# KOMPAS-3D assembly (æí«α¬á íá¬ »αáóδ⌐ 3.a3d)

Referenced files in D:\АСКОН работа\Конкурс HOME\06_Сюваев_Сборная модель танка Т90\ДЕТАЛИ\КОРПУС\МЕТАЛЛ\КОРПУС ШТАМПОВКА\БАКИ\: бак правый 3.m3d
Referenced files in D:\АСКОН работа\Конкурс HOME\06_Сюваев_Сборная модель танка Т90\ДЕТАЛИ\ОБЩИЕ ДЕТАЛИ\: ручки баков.m3d
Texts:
  Сборка бак правый 3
